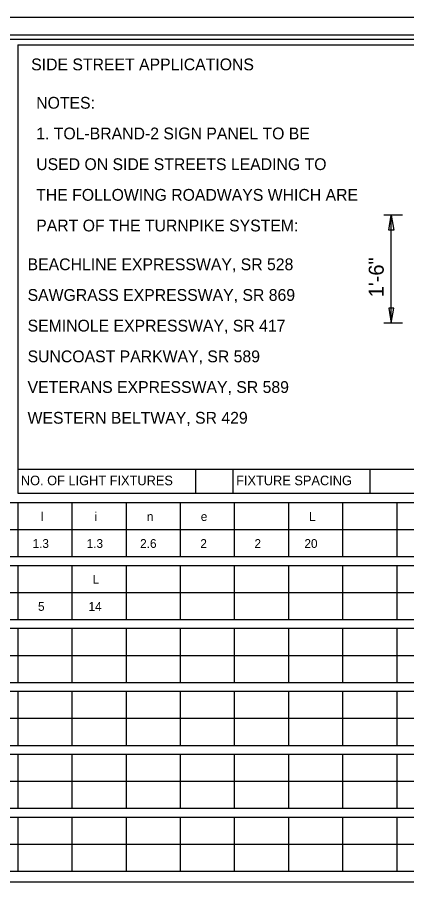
# Model space of a CAD drawing. Extents: x 17890628 to 17890754, y 17897693 to 17897992.
# Drawn here: x 17890694.3 to 17890699.71, y 17897888.7 to 17897900.78 of the extents above; entities that cross this region are included whole.
import ezdxf

# ---------------------------------------------------------------- set-up
doc = ezdxf.new("R2010")
doc.units = 0
for name, color, linetype in [('GSDims', 7, 'Continuous'), ('GSSign', 7, 'Continuous'), ('PlotBorder_dp', 7, 'Continuous'), ('SheetBorder_dp', 7, 'Continuous'), ('SheetLinesMisc2_dp', 7, 'Continuous'), ('TextMinor', 7, 'Continuous'), ('TextMisc', 7, 'Continuous')]:
    doc.layers.add(name, color=color, linetype=linetype)

msp = doc.modelspace()

# ---------------------------------------------------------------- linework, layer by layer
at = {"layer": 'GSDims'}
for p, q in [((17890699.648, 17897898.031), (17890699.388, 17897898.031)), ((17890699.492, 17897896.531), (17890699.492, 17897898.031)), ((17890699.648, 17897898.031), (17890699.648, 17897898.031)), ((17890699.648, 17897896.531), (17890699.388, 17897896.531)), ((17890699.648, 17897896.531), (17890699.648, 17897896.531))]:
    msp.add_line(p, q, dxfattribs=at)
for points in [[(17890699.492, 17897898.031), (17890699.527, 17897897.823), (17890699.457, 17897897.823)], [(17890699.492, 17897896.531), (17890699.527, 17897896.74), (17890699.457, 17897896.74)]]:
    msp.add_lwpolyline(points, close=True, dxfattribs=at)
at = {"layer": 'PlotBorder_dp'}
msp.add_lwpolyline([(17890687.002, 17897874.814), (17890727.417, 17897874.814), (17890727.417, 17897900.777), (17890687.002, 17897900.777)], close=True, dxfattribs=at)
at = {"layer": 'SheetBorder_dp'}
msp.add_line((17890688.35, 17897900.533), (17890726.07, 17897900.533), dxfattribs=at)
at = {"layer": 'SheetLinesMisc2_dp'}
for p, q in [((17890688.417, 17897900.475), (17890726.026, 17897900.475)), ((17890694.303, 17897900.397), (17890707.094, 17897900.397)), ((17890694.303, 17897900.397), (17890694.303, 17897894.166)), ((17890694.303, 17897894.5), (17890707.094, 17897894.5)), ((17890696.773, 17897894.5), (17890696.773, 17897894.166)), ((17890697.291, 17897894.5), (17890697.291, 17897894.166)), ((17890699.196, 17897894.5), (17890699.196, 17897894.166)), ((17890694.303, 17897894.166), (17890707.094, 17897894.166)), ((17890688.597, 17897894.038), (17890707.094, 17897894.038)), ((17890694.303, 17897894.038), (17890694.303, 17897893.286)), ((17890695.055, 17897894.038), (17890695.055, 17897893.286)), ((17890695.807, 17897894.038), (17890695.807, 17897893.286)), ((17890696.56, 17897894.038), (17890696.56, 17897893.286)), ((17890697.312, 17897894.038), (17890697.312, 17897893.286)), ((17890698.065, 17897894.038), (17890698.065, 17897893.286)), ((17890698.817, 17897894.038), (17890698.817, 17897893.286)), ((17890699.57, 17897894.038), (17890699.57, 17897893.286)), ((17890688.597, 17897893.662), (17890707.094, 17897893.662)), ((17890688.597, 17897893.286), (17890707.094, 17897893.286)), ((17890688.597, 17897893.163), (17890707.094, 17897893.163)), ((17890694.303, 17897893.163), (17890694.303, 17897892.412)), ((17890695.055, 17897893.163), (17890695.055, 17897892.412)), ((17890695.807, 17897893.163), (17890695.807, 17897892.412)), ((17890696.56, 17897893.163), (17890696.56, 17897892.412)), ((17890697.312, 17897893.163), (17890697.312, 17897892.412)), ((17890698.065, 17897893.163), (17890698.065, 17897892.412)), ((17890698.817, 17897893.163), (17890698.817, 17897892.412)), ((17890699.57, 17897893.163), (17890699.57, 17897892.412)), ((17890688.597, 17897892.788), (17890707.094, 17897892.788)), ((17890688.597, 17897892.412), (17890707.094, 17897892.412)), ((17890688.597, 17897892.29), (17890707.094, 17897892.29)), ((17890694.303, 17897892.29), (17890694.303, 17897891.538)), ((17890695.055, 17897892.29), (17890695.055, 17897891.538)), ((17890695.807, 17897892.29), (17890695.807, 17897891.538)), ((17890696.56, 17897892.29), (17890696.56, 17897891.538)), ((17890697.312, 17897892.29), (17890697.312, 17897891.538)), ((17890698.065, 17897892.29), (17890698.065, 17897891.538)), ((17890698.817, 17897892.29), (17890698.817, 17897891.538)), ((17890699.57, 17897892.29), (17890699.57, 17897891.538)), ((17890688.597, 17897891.914), (17890707.094, 17897891.914)), ((17890688.597, 17897891.538), (17890707.094, 17897891.538)), ((17890688.597, 17897891.416), (17890707.094, 17897891.416)), ((17890694.303, 17897891.416), (17890694.303, 17897890.664)), ((17890695.055, 17897891.416), (17890695.055, 17897890.664)), ((17890695.807, 17897891.416), (17890695.807, 17897890.664)), ((17890696.56, 17897891.416), (17890696.56, 17897890.664)), ((17890697.312, 17897891.416), (17890697.312, 17897890.664)), ((17890698.065, 17897891.416), (17890698.065, 17897890.664)), ((17890698.817, 17897891.416), (17890698.817, 17897890.664)), ((17890699.57, 17897891.416), (17890699.57, 17897890.664)), ((17890688.597, 17897891.04), (17890707.094, 17897891.04)), ((17890688.597, 17897890.664), (17890707.094, 17897890.664)), ((17890688.597, 17897890.542), (17890707.094, 17897890.542)), ((17890694.303, 17897890.542), (17890694.303, 17897889.79)), ((17890695.055, 17897890.542), (17890695.055, 17897889.79)), ((17890695.807, 17897890.542), (17890695.807, 17897889.79)), ((17890696.56, 17897890.542), (17890696.56, 17897889.79)), ((17890697.312, 17897890.542), (17890697.312, 17897889.79)), ((17890698.065, 17897890.542), (17890698.065, 17897889.79)), ((17890698.817, 17897890.542), (17890698.817, 17897889.79)), ((17890699.57, 17897890.542), (17890699.57, 17897889.79)), ((17890688.597, 17897890.166), (17890707.094, 17897890.166)), ((17890688.597, 17897889.79), (17890707.094, 17897889.79)), ((17890688.597, 17897889.668), (17890707.094, 17897889.668)), ((17890694.303, 17897889.668), (17890694.303, 17897888.916)), ((17890695.055, 17897889.668), (17890695.055, 17897888.916)), ((17890695.807, 17897889.668), (17890695.807, 17897888.916)), ((17890696.56, 17897889.668), (17890696.56, 17897888.916)), ((17890697.312, 17897889.668), (17890697.312, 17897888.916)), ((17890698.065, 17897889.668), (17890698.065, 17897888.916)), ((17890698.817, 17897889.668), (17890698.817, 17897888.916)), ((17890699.57, 17897889.668), (17890699.57, 17897888.916)), ((17890688.597, 17897889.292), (17890707.094, 17897889.292)), ((17890688.597, 17897888.916), (17890707.094, 17897888.916)), ((17890688.417, 17897888.769), (17890726.026, 17897888.769))]:
    msp.add_line(p, q, dxfattribs=at)

# ---------------------------------------------------------------- texts
at = {"layer": 'GSDims'}
msp.add_text('1\'-6"', height=0.2083, rotation=90, dxfattribs=at).set_placement((17890699.388, 17897896.889))
at = {"layer": 'GSSign'}
for s, height, p in [('l', 0.122, (17890694.624, 17897893.782)), ('i', 0.122, (17890695.371, 17897893.782)), ('n', 0.122, (17890696.097, 17897893.782)), ('e', 0.122, (17890696.846, 17897893.782)), ('L', 0.122, (17890698.35, 17897893.782)), ('1.3', 0.1225, (17890694.508, 17897893.407)), ('1.3', 0.1225, (17890695.26, 17897893.407)), ('2.6', 0.1225, (17890696.003, 17897893.407)), ('2', 0.122, (17890696.84, 17897893.407)), ('2', 0.122, (17890697.592, 17897893.407)), ('20', 0.1225, (17890698.286, 17897893.407)), ('L', 0.122, (17890695.342, 17897892.909)), ('5', 0.122, (17890694.584, 17897892.533)), ('14', 0.1225, (17890695.286, 17897892.533))]:
    msp.add_text(s, height=height, dxfattribs=at).set_placement(p)
at = {"layer": 'TextMinor'}
for s, p in [('NO. OF LIGHT FIXTURES', (17890694.346, 17897894.278)), ('FIXTURE SPACING', (17890697.337, 17897894.278))]:
    msp.add_text(s, height=0.13286, dxfattribs=at).set_placement(p)
at = {"layer": 'TextMisc'}
for s, p in [('SIDE STREET APPLICATIONS', (17890694.489, 17897900.042)), ('NOTES:', (17890694.559, 17897899.509)), ('1. TOL-BRAND-2 SIGN PANEL TO BE', (17890694.559, 17897899.083)), ('USED ON SIDE STREETS LEADING TO', (17890694.559, 17897898.656)), ('THE FOLLOWING ROADWAYS WHICH ARE', (17890694.559, 17897898.23)), ('PART OF THE TURNPIKE SYSTEM:', (17890694.559, 17897897.804)), ('BEACHLINE EXPRESSWAY, SR 528', (17890694.439, 17897897.265)), ('SAWGRASS EXPRESSWAY, SR 869', (17890694.439, 17897896.839)), ('SEMINOLE EXPRESSWAY, SR 417', (17890694.439, 17897896.413)), ('SUNCOAST PARKWAY, SR 589', (17890694.439, 17897895.986)), ('VETERANS EXPRESSWAY, SR 589', (17890694.439, 17897895.56)), ('WESTERN BELTWAY, SR 429', (17890694.439, 17897895.133))]:
    msp.add_text(s, height=0.164, dxfattribs=at).set_placement(p)

doc.saveas('drawing.dxf')
